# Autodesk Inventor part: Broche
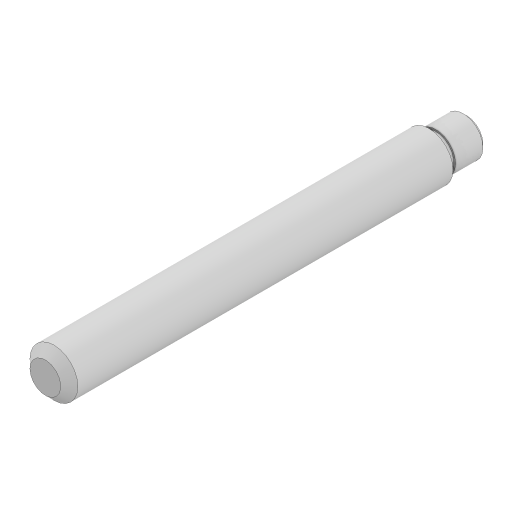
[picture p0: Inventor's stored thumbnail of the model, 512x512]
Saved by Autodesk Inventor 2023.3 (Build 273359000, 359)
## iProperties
Created: 2024-11
Part Number: Broche
Material: Générique
Description: STEP AP203
Document SubType Name: Modeling
Designer: Thier
Density: 1 g/cm^3
Appearance: Par défaut
Title: Broche.STEP
Revision Number: ANY
Sending System: SolidWorks 2017
Preprocessor: SwSTEP 2.0
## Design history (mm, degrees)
feature "Chanfrein2"
node "Solide1"
